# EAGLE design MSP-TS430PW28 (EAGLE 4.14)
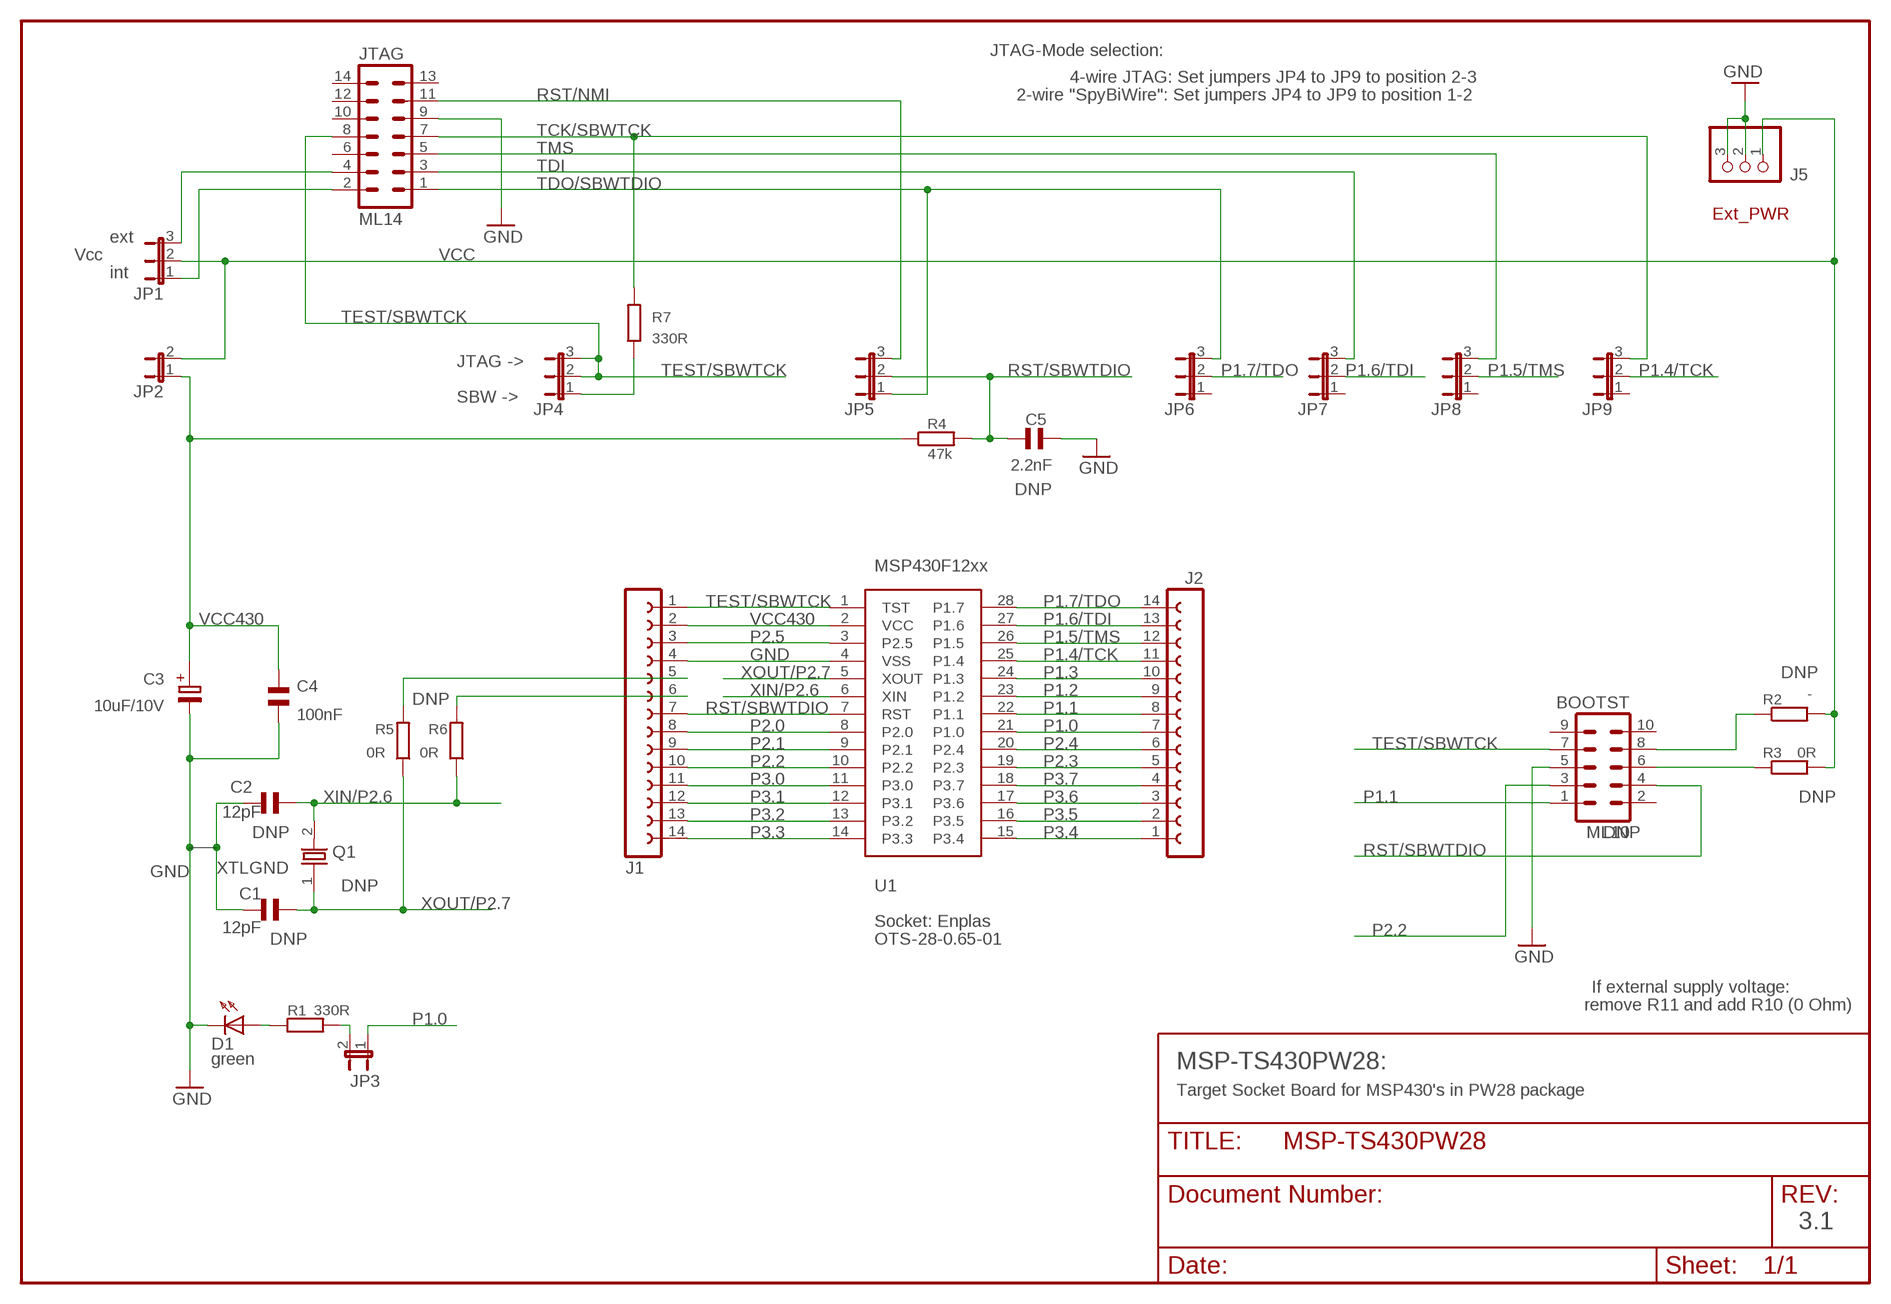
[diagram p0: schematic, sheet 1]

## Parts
BOOTST  ML10  [ML10]
C1  12pF  CSMD0805  [CSMD0805]
C2  12pF  CSMD0805  [CSMD0805]
C3  10uF/10V  ELKO_1210  [1210ELKO]
C4  100nF  CSMD0805  [CSMD0805]
C5  2.2nF  CSMD0805  [CSMD0805]
D1  green  LED_0603D0603  [DIODE0603]
J1  FE14-1  [FE14]
J2  FE14-1  [FE14]
J5  PINHD-1X3  [1X03]
JP1  JP2E  [JP2]
JP2  JP1E  [JP1]
JP3  JP1E  [JP1]
JP4  JP2E  [JP2]
JP5  JP2E  [JP2]
JP6  JP2E  [JP2]
JP7  JP2E  [JP2]
JP8  JP2E  [JP2]
JP9  JP2E  [JP2]
JTAG  ML14  [ML14]
Q1  HCTC_XTLTCV  [TCV]
R1  330R  R_0805  [0805]
R2  -  R_0805  [0805]
R3  0R  R_0805  [0805]
R4  47k  R_0805  [0805]
R5  0R  R_0805  [0805]
R6  0R  R_0805  [0805]
R7  330R  R_0805  [0805]
U1  F12XXSOCK28PW  [SOCK28PW]

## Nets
GND: BOOTST.5 C3.- C4.2 C5.2 D1.K(C) J1.4 J5.2 J5.3 JTAG.9 U1.4(VSS)
N$1: J1.5 R5.2
N$2: J1.6 R6.2
N$3: JP4.1 R7.1
N$7: JP1.1 JTAG.2
N$23: JP1.3 JTAG.4
N$33: JP3.2 R1.2
N$34: D1.A R1.1
N$42: BOOTST.8 R2.1
N$49: BOOTST.6 R3.1
P1.0: J2.7 JP3.1 U1.21(P1.0)
P1.1: BOOTST.1 J2.8 U1.22(P1.1)
P1.2: J2.9 U1.23(P1.2)
P1.3: J2.10 U1.24(P1.3)
P1.4/TCK: J2.11 JP9.2 U1.25(P1.4)
P1.5/TMS: J2.12 JP8.2 U1.26(P1.5)
P1.6/TDI: J2.13 JP7.2 U1.27(P1.6)
P1.7/TDO: J2.14 JP6.2 U1.28(P1.7)
P2.0: J1.8 U1.8(P2.0)
P2.1: J1.9 U1.9(P2.1)
P2.2: BOOTST.3 J1.10 U1.10(P2.2)
P2.3: J2.5 U1.19(P2.3)
P2.4: J2.6 U1.20(P2.4)
P2.5: J1.3 U1.3(P2.5)
P3.0: J1.11 U1.11(P3.0)
P3.1: J1.12 U1.12(P3.1)
P3.2: J1.13 U1.13(P3.2)
P3.3: J1.14 U1.14(P3.3)
P3.4: J2.1 U1.15(P3.4)
P3.5: J2.2 U1.16(P3.5)
P3.6: J2.3 U1.17(P3.6)
P3.7: J2.4 U1.18(P3.7)
RST/NMI: JP5.3 JTAG.11
RST/SBWTDIO: BOOTST.4 C5.1 J1.7 JP5.2 R4.2 U1.7(RST)
TCK/SBWTCK: JP9.3 JTAG.7 R7.2
TDI: JP7.3 JTAG.3
TDO/SBWTDIO: JP5.1 JP6.3 JTAG.1
TEST/SBWTCK: BOOTST.7 J1.1 JP4.2 JP4.3 JTAG.8 U1.1(TST)
TMS: JP8.3 JTAG.5
VCC: J5.1 JP1.2 JP2.2 R2.2 R3.2
VCC430: C3.+ C4.1 J1.2 JP2.1 R4.1 U1.2(VCC)
XIN/P2.6: C2.1 Q1.2 R6.1 U1.6(XIN)
XOUT/P2.7: C1.1 Q1.1 R5.1 U1.5(XOUT)
XTLGND: C1.2 C2.2
Unconnected: BOOTST.2 BOOTST.9 BOOTST.10 JP6.1 JP7.1 JP8.1 JP9.1 JTAG.6 JTAG.10 JTAG.12 JTAG.13 JTAG.14

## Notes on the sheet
- JTAG-Mode selection:
- 4-wire JTAG: Set jumpers JP4 to JP9 to position 2-3
- 2-wire "SpyBiWire": Set jumpers JP4 to JP9 to position 1-2
- Ext_PWR
- ext
- Vcc
- int
- JTAG ->
- SBW ->
- DNP
- DNP
- DNP
- DNP
- DNP | DNP
- DNP
- Socket: Enplas
- DNP | OTS-28-0.65-01
- If external supply voltage:
- remove R11 and add R10 (0 Ohm)
- MSP-TS430PW28:
- Target Socket Board for MSP430's in PW28 package
- 3.1

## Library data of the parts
BOOTST = con-ml:ML10
C1 C2 C4 C5 = cap:CSMD0805
C3 = smd:ELKO_1210
D1 = smd:LED_0603
J1 J2 = scon-lsta:FE14-1
J5 = PINHEAD:PINHD-1X3: PIN HEADER
JP1 JP4-JP9 = jumper:JP2E: JUMPER
JP2 JP3 = jumper:JP1E: JUMPER
JTAG = con-ml:ML14
Q1 = scrystal:HCTC_XTL
R1-R7 = smd:R_0805
U1 = smsp430_flash:F12XX: This device supports following MSP430 derivatives: MSP430F122, MSP430F123, MSP430F1222, MSP430F1232 in 28pin DW and PW packages.

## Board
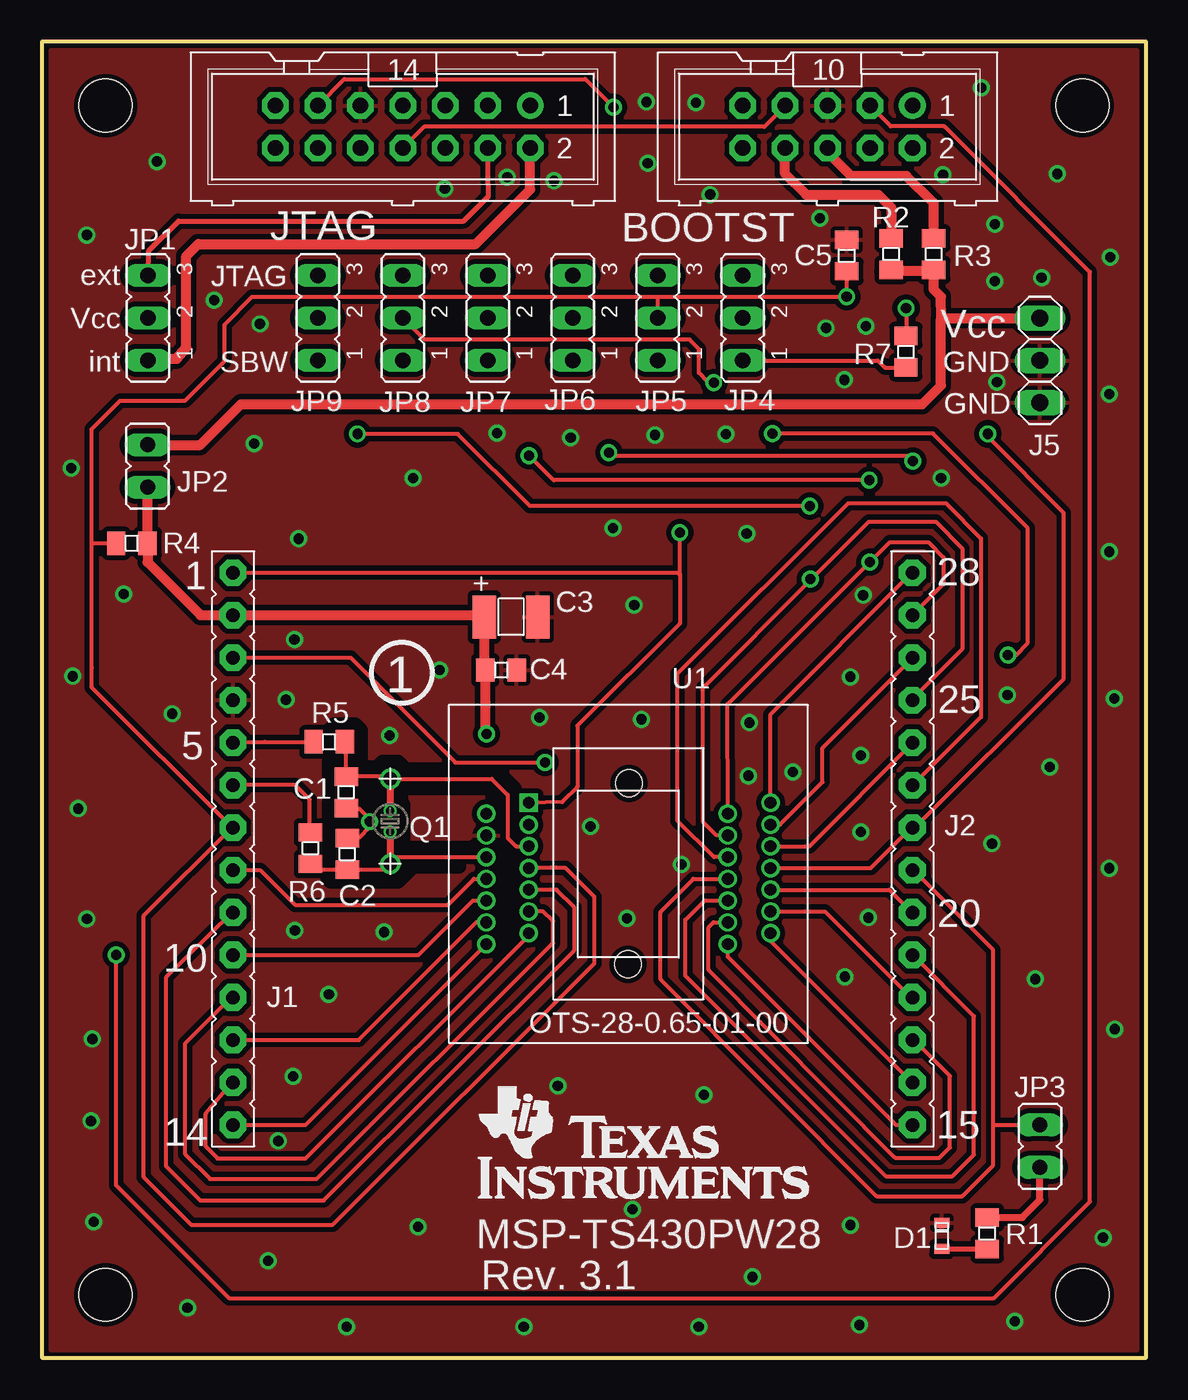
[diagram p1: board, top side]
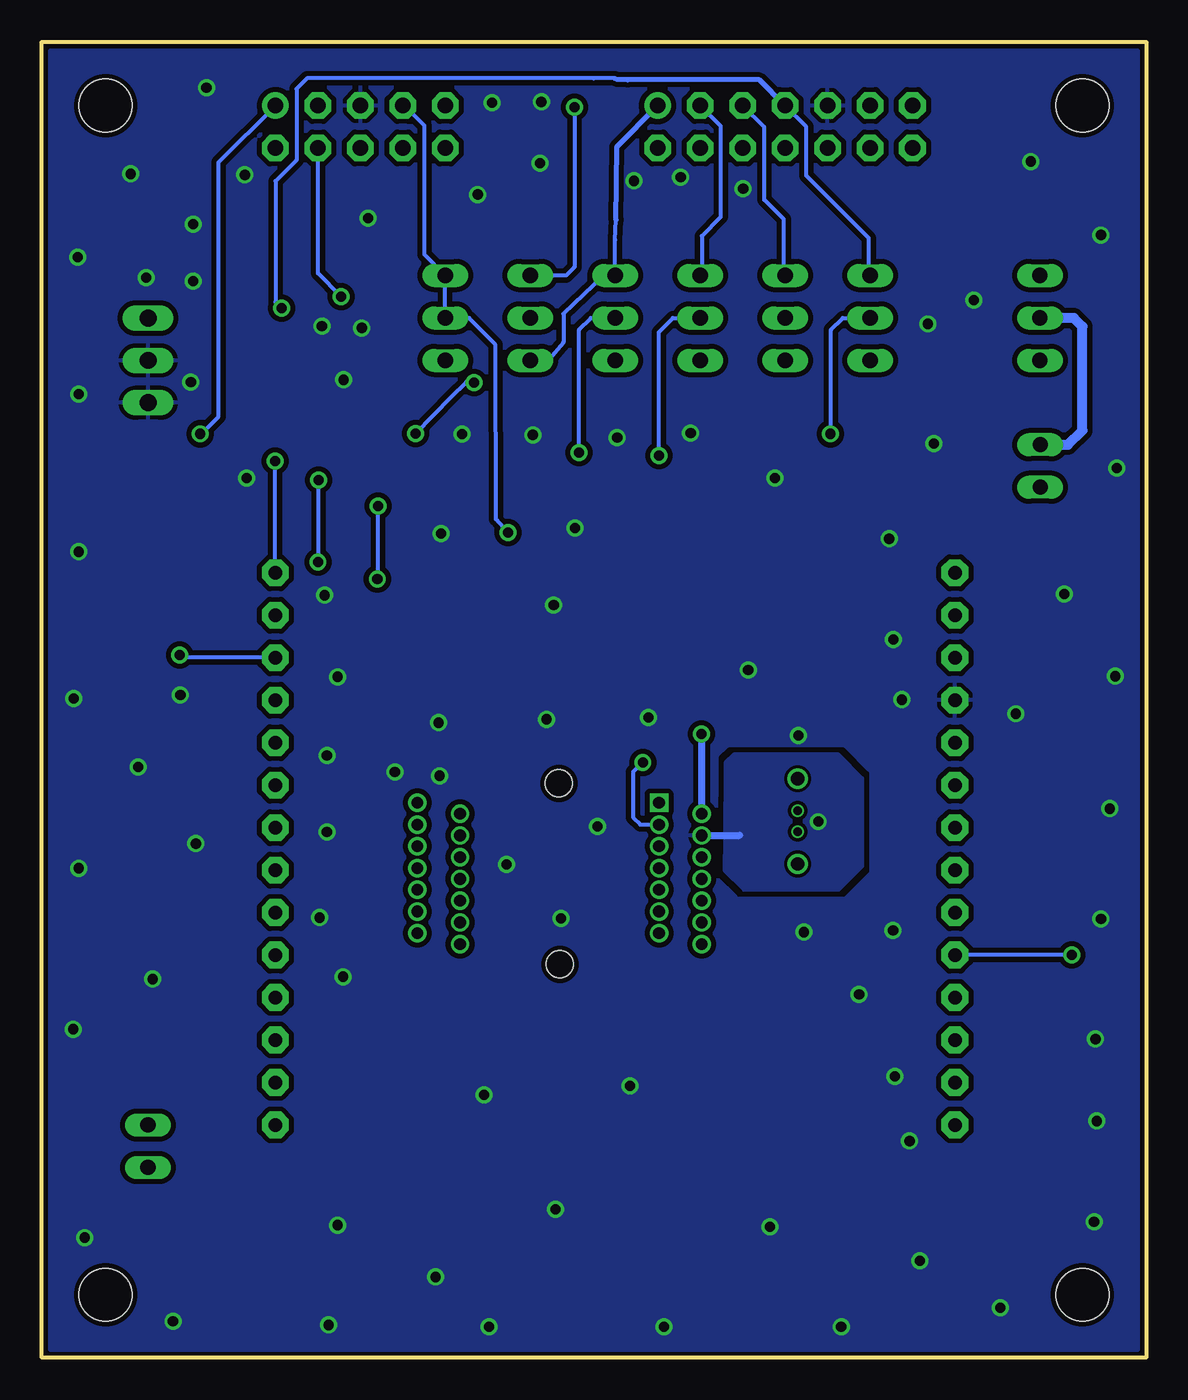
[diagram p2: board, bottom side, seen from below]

Size 66.04 x 78.69 mm. Coordinates in mm from the lower left corner, seen from the top.
Outline: 0,78.69 0,0 66.04,0 66.04,78.69 0,78.69
Copper layers (1*16): Top 0.035mm / dielectric 1.5mm / Bottom 0.035mm
Design rules "default": minimum track width 10mil, minimum drill 0.4mm, track to track 0.2mm, track to pad 0.2mm, pad to pad 0.19mm, via to via 0.2mm, smd to smd 8mil, copper to edge 0mil, drill to drill 8mil, minimum pad ring 5mil, minimum via ring 8mil, stop-mask expansion 4mil, vias tented up to drill 0.4mm, thermal gap 10mil
Holes 3.15 mm at 3.81,74.88 62.23,74.88 62.23,3.76 3.81,3.76
tRestrict: 29 lines

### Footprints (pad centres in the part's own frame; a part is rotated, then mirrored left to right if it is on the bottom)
ML10 = drill 0.914 pad 1.6 round: 1 -5.08,-1.27 | drill 0.914 pad 1.6 octagon: 2 -5.08,1.27; 3 -2.54,-1.27; 4 -2.54,1.27; 5 0,-1.27; 6 0,1.27; 7 2.54,-1.27; 8 2.54,1.27; 9 5.08,-1.27; 10 5.08,1.27
CSMD0805 = smd 1.092 x 1.397: 1 -0.94,0; 2 0.94,0
1210ELKO = smd 1.397 x 2.591: + 1.6,0; - -1.6,0
DIODE0603 = smd 0.6 x 0.9: A -0.787,0; K 0.787,0
FE14 = drill 0.813 pad 1.6 octagon: 1 -16.51,0; 2 -13.97,0; 3 -11.43,0; 4 -8.89,0; 5 -6.35,0; 6 -3.81,0; 7 -1.27,0; 8 1.27,0; 9 3.81,0; 10 6.35,0; 11 8.89,0; 12 11.43,0; 13 13.97,0; 14 16.51,0
1X03 = drill 1.016 long: 1 -2.54,0; 2 0,0; 3 2.54,0
JP2 = drill 0.914 long: 1 -2.54,0; 2 0,0; 3 2.54,0
JP1 = drill 0.914 long: 1 0,-1.27; 2 0,1.27
ML14 = drill 0.914 pad 1.6 round: 1 -7.62,-1.27 | drill 0.914 pad 1.6 octagon: 2 -7.62,1.27; 3 -5.08,-1.27; 4 -5.08,1.27; 5 -2.54,-1.27; 6 -2.54,1.27; 7 0,-1.27; 8 0,1.27; 9 2.54,-1.27; 10 2.54,1.27; 11 5.08,-1.27; 12 5.08,1.27; 13 7.62,-1.27; 14 7.62,1.27
TCV = drill 0.5 round: 1 -0.635,0; 2 0.635,0
0805 = smd 1.092 x 1.397: 1 -0.94,0; 2 0.94,0
SOCK28PW = drill 0.7 pad 1.1 square: 1 5.95,-4.25 | drill 0.7 pad 1.1 round: 2 8.5,-3.6; 3 5.95,-2.95; 4 8.5,-2.3; 5 5.95,-1.65; 6 8.5,-1; 7 5.95,-0.35; 8 8.5,0.3; 9 5.95,0.95; 10 8.5,1.6; 11 5.95,2.25; 12 8.5,2.9; 13 5.95,3.55; 14 8.5,4.2; 15 -5.95,4.2; 16 -8.5,3.55; 17 -5.95,2.9; 18 -8.5,2.25; 19 -5.95,1.6; 20 -8.5,0.95; 21 -5.95,0.3; 22 -8.5,-0.35; 23 -5.95,-1; 24 -8.5,-1.65; 25 -5.95,-2.3; 26 -8.5,-2.95; 27 -5.95,-3.6; 28 -8.5,-4.25 | hole 1.6: -0.04,-5.42; 0.02,5.4

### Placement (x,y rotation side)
BOOTST  46.99,73.61 180 top
C1  18.2,33.8 270 top
C2  18.26,30.12 90 top
C3  28.06,44.29 180 top
C4  27.46,41.13 0 top
C5  48.14,65.91 90 top
D1  53.82,7.29 90 top
J1  11.43,30.43 270 top
J2  52.07,30.43 90 top
J5  59.69,59.64 270 top
JP1  6.35,62.18 90 top
JP2  6.33,53.33 0 top
JP3  59.69,12.65 180 top
JP4  41.91,62.18 90 top
JP5  36.83,62.18 90 top
JP6  31.75,62.18 90 top
JP7  26.67,62.18 90 top
JP8  21.59,62.18 90 top
JP9  16.51,62.18 90 top
JTAG  21.59,73.61 180 top
Q1  20.83,32.08 270 top
R1  56.54,7.44 90 top
R2  50.8,65.99 270 top
R3  53.34,65.99 270 top
R4  5.38,48.7 180 top
R5  17.19,36.83 180 top
R6  16.06,30.47 90 top
R7  51.68,60.16 90 top
U1  35.08,28.93 180 top
U$1  [LABELS_TPLACE]  34.98,10.8 0 top

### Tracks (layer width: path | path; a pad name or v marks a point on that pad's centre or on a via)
GND  (via drill 0.61)
  other vias: 63.9,65.82 2.7,67.14 3.03,19.05 8.71,2.98 59.79,64.59 6.89,71.53 63.47,7.18 64.17,19.65 63.84,29.27 64.14,39.42 63.84,48.2 63.84,57.62 1.76,53.19 1.85,40.75 2.18,32.83 2.7,26.24 3.11,8.13 59.41,22.64 56.83,30.74 12.69,54.67 60.28,35.33 22.2,52.6 36.17,75.09 36.24,71.44 39.12,75.05 39.97,69.56 56.19,75.94 60.73,70.79 49.29,61.68 47.99,58.48 46.9,61.58 13.04,61.82 10.3,63.24 2.94,14.15 58.2,2.18 57,67.79 57,64.38 57.12,58.34 46.53,68.14 30.63,70.37 27.83,70.6 24.1,69.91 4.9,45.67 7.79,38.51 15.36,48.97 34.16,49.61 42.16,49.28 35.86,38.18 35.43,45.01 29.76,38.28 14.6,39.35 20.8,37.21 15.13,25.55 20.47,25.45 17.17,21.72 15.03,16.82 13.53,5.79 18.23,1.86 28.82,1.86 39.29,1.86 48.89,1.96 22.5,7.82 30.86,16.26 39.59,15.72 48.36,7.93 42.49,4.83 35.33,8.87 48.03,22.79 49.42,26.32 48.99,31.45 48.99,36.02 48.36,40.72 42.31,37.97 42.26,34.8 32.81,31.78 38.25,29.49 35,26.26 23.8,41.12 15.11,42.95 53.9,70.73 49.12,45.59 14.14,12.96 44.93,35.03 57.75,39.62 53.79,52.61 40.91,55.24 36.67,55.18 31.63,55.02 27.23,55.29
  pour Bottom (isolate 0.305, rank 2): 0.51,78.18 0.51,0.46 65.53,0.46 65.53,78.18
  pour Top (isolate 0.305): 0.51,78.18 0.51,0.46 65.53,0.46 65.53,78.18
N$1
  Top 0.254: R5.2 13.35,36.83 11.48,36.83 11.48,36.78 J1.5
N$2
  Top 0.254: R6.2 16.04,30.97 16.03,30.96 16.03,33.38 15.16,34.24 J1.6 11.4,34.24
N$3
  Top 0.254: 51.37,59.22 R7.1 51.65,59.22 51.64,59.21 50.42,59.21 49.99,59.64 JP4.1
N$7
  Top 0.3: JTAG.2 29.21,72.41 | JP1.1 6.8,59.74
  Top 0.61: JTAG.2 29.21,69.86 25.95,66.6 9.36,66.6 8.64,65.88 8.64,60.4 8.07,59.74 6.8,59.74
N$23
  Top 0.3: JTAG.4 26.66,72.36 26.71,69.45 25.23,67.97 8.18,67.97 6.4,66.2 JP1.3
N$33
  Top 0.406: JP3.2 59.69,9.45 58.65,8.38 R1.2
N$34
  Top 0.305: D1.A R1.1
N$42
  Top 0.61: R2.1 50.8,68.78 50.04,69.55 45.72,69.55 44.45,70.82 BOOTST.8
N$49
  Top 0.3: 46.99,72.09 BOOTST.6
  Top 0.61: R3.1 53.34,69.04 51.72,70.66 48.41,70.66 46.99,72.09
P1.0
  Top 0.254: U1.21 38.97,28.63 37.01,26.64 37.01,22.63 49.91,9.65 55.04,9.65 56.9,11.51 56.9,13.89 | J2.7 52.12,29.16 56.9,24.38 56.9,13.89 | 56.9,13.89 57.02,13.92 57.43,13.92 JP3.1
P1.1  (via drill 0.6)
  Top 0.254: U1.22 49.58,29.28 51.99,31.7 J2.8 52.22,31.7 61.11,40.59 61.11,50.52 56.59,55.04 v56.57,55.25
  Bottom 0.254: BOOTST.1 55.47,71.48 55.47,56.29 56.52,55.25 v56.57,55.25
P1.2
  Top 0.254: U1.23 40.2,29.93 38.02,32.11 38.02,40.92 48.23,51.11 54.08,51.11 56.16,49 56.16,38.3 52.09,34.24 J2.9
P1.3
  Top 0.254: J2.10 52.09,36.78 45.9,30.58 U1.24
P1.4/TCK  (via drill 0.6)
  Top 0.254: U1.25 40.35,31.23 39.55,32.03 39.55,40.06 45.98,46.5 | 45.98,46.5 49.45,49.99 53.47,49.99 55.04,48.39 55.04,42.37 52.07,39.4 J2.11 | v18.87,55.25 24.87,55.25 29.18,50.93 v45.92,50.93 | 45.98,46.5 45.97,46.51 v45.97,46.56
  Bottom 0.254: J2.11 52.12,39.32 52.17,39.27 52.27,39.37 | JP9.2 18.14,62.18 18.85,61.47 18.85,55.27 v18.87,55.25 18.85,55.25 | v45.92,50.93 45.92,46.61 v45.97,46.56
P1.5/TMS  (via drill 0.6)
  Top 0.254: JP8.2 22.88,60.88 38.73,60.88 39.29,60.33 39.29,58.9 39.88,58.32 v40.18,58.32 | U1.26 44.15,31.88 46.69,34.42 46.69,36.45 52.07,41.83 J2.12 | v43.69,55.27 53.29,55.27 58.95,49.61 58.95,42.75 58.27,42.01 v57.79,42.01
  Bottom 0.254: v40.18,58.32 40.64,58.34 41.53,57.48 v43.69,55.27 | J2.12 52.09,41.88 57.28,41.88 v57.79,42.01
P1.6/TDI  (via drill 0.6)
  Top 0.254: U1.27 41,39.07 v49.53,47.58 | v49.53,47.58 49.55,47.6 | 49.55,47.6 50.72,48.77 53.01,48.77 53.92,47.85 53.92,46.25 J2.13 | v29.13,53.95 30.61,52.48 v49.48,52.48 | 49.55,47.6 49.53,47.63 49.53,47.62 v49.53,47.58 | 49.55,47.6
  Bottom 0.254: JP7.2 28.3,62.18 29.13,61.32 v29.13,53.95 | J2.13 52.05,44.42 | v49.53,47.57 v49.53,47.58 49.48,47.63 v49.48,52.48
P1.7/TDO  (via drill 0.6)
  Top 0.254: J2.14 52.05,46.94 43.58,38.47 U1.28 | v33.91,54.13 34.19,53.92 51.77,53.92 52.07,53.62 v52.09,53.62
  Bottom 0.254: JP6.2 33.2,62.18 33.91,61.47 v33.91,54.13 | J2.14 52.09,46.96 v52.09,53.62
P2.0
  Top 0.254: U1.8 25.84,28.63 24.28,27.08 15.14,27.08 13.06,29.16 J1.8
P2.1
  Top 0.254: U1.9 30.79,27.98 31.85,26.92 31.85,24.36 16.87,9.4 9.47,9.4 7.44,11.43 7.44,22.76 11.38,26.62 J1.9
P2.2  (via drill 0.6)
  Top 0.254: BOOTST.3 50.78,73.63 53.98,73.63 62.69,64.92 62.69,9.32 56.92,3.56 11.2,3.56 4.45,10.31 v4.45,24.08 | U1.10 25.78,27.33 22.53,24.08 J1.10
  Bottom 0.254: v4.45,24.08 J1.10
P2.3
  Top 0.254: U1.19 39.65,27.33 38.48,26.19 38.48,22.83 50.47,10.85 54.46,10.85 55.75,12.14 55.75,20.42 52.09,24.08 J2.5
P2.4
  Top 0.254: J2.6 52.07,26.59 50.68,27.98 U1.20
P2.5  (via drill 0.6)
  Top 0.254: v30.1,35.59 24.74,35.59 18.47,41.86 J1.3
  Bottom 0.254: U1.3 30.25,31.88 30.68,32.31 30.68,35.03 v30.1,35.59
P3.0
  Top 0.254: U1.11 29.99,26.68 30.58,26.11 30.58,24.79 16.43,10.69 10.06,10.69 8.59,12.17 8.59,18.8 11.33,21.54 J1.11
P3.1
  Top 0.254: U1.12 25.98,26.03 18.95,19 J1.12
P3.2
  Top 0.254: U1.13 29.13,25.27 15.77,11.91 10.52,11.91 9.8,12.65 9.8,14.61 11.38,16.46 J1.13
P3.3
  Top 0.254: U1.14 15.77,13.92 11.48,13.92 11.46,13.89 J1.14
P3.4
  Top 0.254: U1.15 41.03,23.97 51.08,13.92 J2.1
P3.5
  Top 0.254: J2.2 52.07,16.43 43.58,24.93 U1.16
P3.6
  Top 0.254: U1.17 40.18,26.03 39.88,25.73 39.88,23.19 51.03,11.96 53.67,11.96 54.3,12.57 54.3,16.84 52.15,19 J2.3
P3.7
  Top 0.254: J2.4 52.02,21.54 51.99,21.51 46.83,26.68 U1.18
RST/NMI  (via drill 0.6)
  Top 0.254: JTAG.11 18.09,76.45 32.51,76.45 v34.19,74.78
  Bottom 0.254: v34.19,74.78 34.19,65.23 34.7,64.72 JP5.3
RST/SBWTDIO  (via drill 0.6)
  Top 0.254: 2.98,48.72 3,41.25 3,40.08 11.38,31.7 J1.7 11.4,31.72 6.1,26.44 6.1,10.8 8.94,7.95 17.4,7.95 33.05,23.57 33.05,27.56 31.32,29.28 U1.7 | 2.98,48.72 2.97,55.52 4.67,57.23 8.56,57.23 10.92,59.59 10.92,61.77 12.57,63.45 36.8,63.45 | JP5.2 36.8,62.2 36.8,63.45 | 2.98,48.72 4.43,48.72 R4.2 | 48.14,64.9 48.13,64.9 | 48.14,64.9 C5.1 | 36.8,63.45 v48.13,63.45 v48.14,63.45 48.14,64.9
  Bottom 0.254: BOOTST.4 49.53,64.85 v48.13,63.45
TCK/SBWTCK  (via drill 0.6)
  Top 0.254: R7.2 51.68,61.18 51.69,61.19 v51.69,62.76
  Bottom 0.254: 31.78,76.5 33.03,76.51 50.18,76.51 50.81,75.88 50.81,71.61 52.06,70.36 52.06,63.13 v51.69,62.76 | JTAG.7 20.32,73.61 20.32,70.69 16.59,66.95 16.59,64.8 JP9.3
  Bottom 0.3: JTAG.7 23.12,76.41 31.01,76.41 31.63,76.43 31.78,76.5
TDI
  Bottom 0.254: JTAG.3 25.42,73.63 25.42,68.22 26.57,67.08 26.57,64.82 JP7.3
TDO/SBWTDIO
  Top 0.254: JP6.3 31.77,64.69
  Bottom 0.254: 31.7,68.03 31.75,66.85 31.75,64.77 31.72,64.74 JP6.3 31.72,64.69 | JP5.1 36.78,59.69 35.71,59.69 34.85,60.71 34.85,62.43 32.44,64.69 31.72,64.69 | 31.72,64.69 31.67,64.64
  Bottom 0.3: JTAG.1 31.65,72.42 31.7,68.03
TEST/SBWTCK  (via drill 0.6)
  Top 0.254: JTAG.8 22.86,73.61 43.21,73.61 44.37,74.78 44.37,74.9 44.43,74.9 BOOTST.7 | 38.15,46.89 38.15,43.92 32.03,37.8 32.03,34.14 31.11,33.22 U1.1 | 38.15,46.89 v38.15,49.35 | 38.15,46.89 38.1,46.89 38.05,46.94 J1.1
  Bottom 0.254: BOOTST.7 44.35,74.88 43.16,73.69 43.16,65.96 JP4.3 JP4.2 40.49,62.18 38.91,60.58 38.89,50.14 v38.15,49.35
TMS
  Bottom 0.254: JTAG.5 22.83,73.58 22.83,69.24 21.67,68.07 21.67,64.8 JP8.3
VCC
  Top 0.3: R3.2 53.26,64.97 | R2.2 50.8,64.97 50.22,64.97
  Top 0.61: 53.26,64.97 50.8,64.97 | R3.2 53.34,63.88 53.77,63.45 53.77,63.42 53.8,62.18 53.85,62.18 | 53.85,62.18 J5.1 | JP2.2 6.35,54.58 9.47,54.58 11.91,57.02 52.65,57.02 53.77,58.14 53.77,62.13 53.85,62.2 53.85,62.18
  Bottom 0.61: JP1.2 4.32,62.18 3.81,61.67 3.81,55.45 4.67,54.6 JP2.2 | J5.1 59.41,62.18
VCC430  (via drill 0.6)
  Top 0.254: JP2.1
  Top 0.61: JP2.1 R4.1 6.33,47.57 9.5,44.4 11.35,44.4 11.38,44.42 11.4,44.4 J1.2 26.14,44.4 26.29,44.25 26.33,44.29 C3.+ 26.46,41.26 26.52,41.2 C4.1 26.52,37.41 26.62,37.31 v26.59,37.29
  Bottom 0.254: v26.59,37.29 26.58,37.27
  Bottom 0.406: 26.58,37.27 U1.2
XIN/P2.6  (via drill 0.8)
  Top 0.254: v20.83,29.52 20.5,29.18 C2.1 16.15,29.18 16.04,29.3 R6.1 | v20.83,29.52 20.85,29.54 20.8,29.54 20.82,29.52 | Q1.2 | Q1.2 | 20.85,31.45 Q1.2 | 20.85,29.67 20.95,29.67 21.22,29.93 U1.6 | v20.83,29.52 20.83,29.52 | 20.83,29.52 v20.84,29.52 | 20.83,29.52
  Top 0.406: 20.85,29.54 20.85,29.67 20.85,31.45
XOUT/P2.7  (via drill 0.8)
  Top 0.254: 20.85,34.62 20.83,34.62 | 20.83,34.62 20.7,34.74 C1.1 18.2,36.74 18.13,36.81 R5.1 | Q1.1 20.83,32.79 20.9,32.72 | U1.5 28.37,30.58 27.86,31.09 27.86,33.66 26.9,34.62 20.9,34.62 20.85,34.57 | v20.84,34.62 v20.83,34.62 20.83,34.62
  Top 0.406: 20.85,34.62 20.85,34.57 20.85,32.82 20.83,32.79
XTLGND  (via drill 0.6)
  Top 0.254: C1.2 18.27,32.86 18.31,32.82 19,32.82 19.61,32.21 v19.61,32.06 19.61,31.72 19,31.12 18.34,31.12 18.29,31.06 C2.2
  Bottom 0.406: 26.26,31.24 24.31,31.24
  pour Bottom: 24.61,36.09 18.44,36.09 16.99,34.65 16.99,29.39 18.41,27.97 24.03,27.97 25.17,29.11 25.15,31.14 25.15,33.17 25.12,33.3 25.12,35.61

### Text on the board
tPlace: ext | Vcc | Vcc | int | GND | GND | 1 | 28 | 1 | 25 | 5 | 20 | 10 | 14 | 15
tNames: JTAG | SBW | MSP-TS430PW28 | Rev. 3.1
